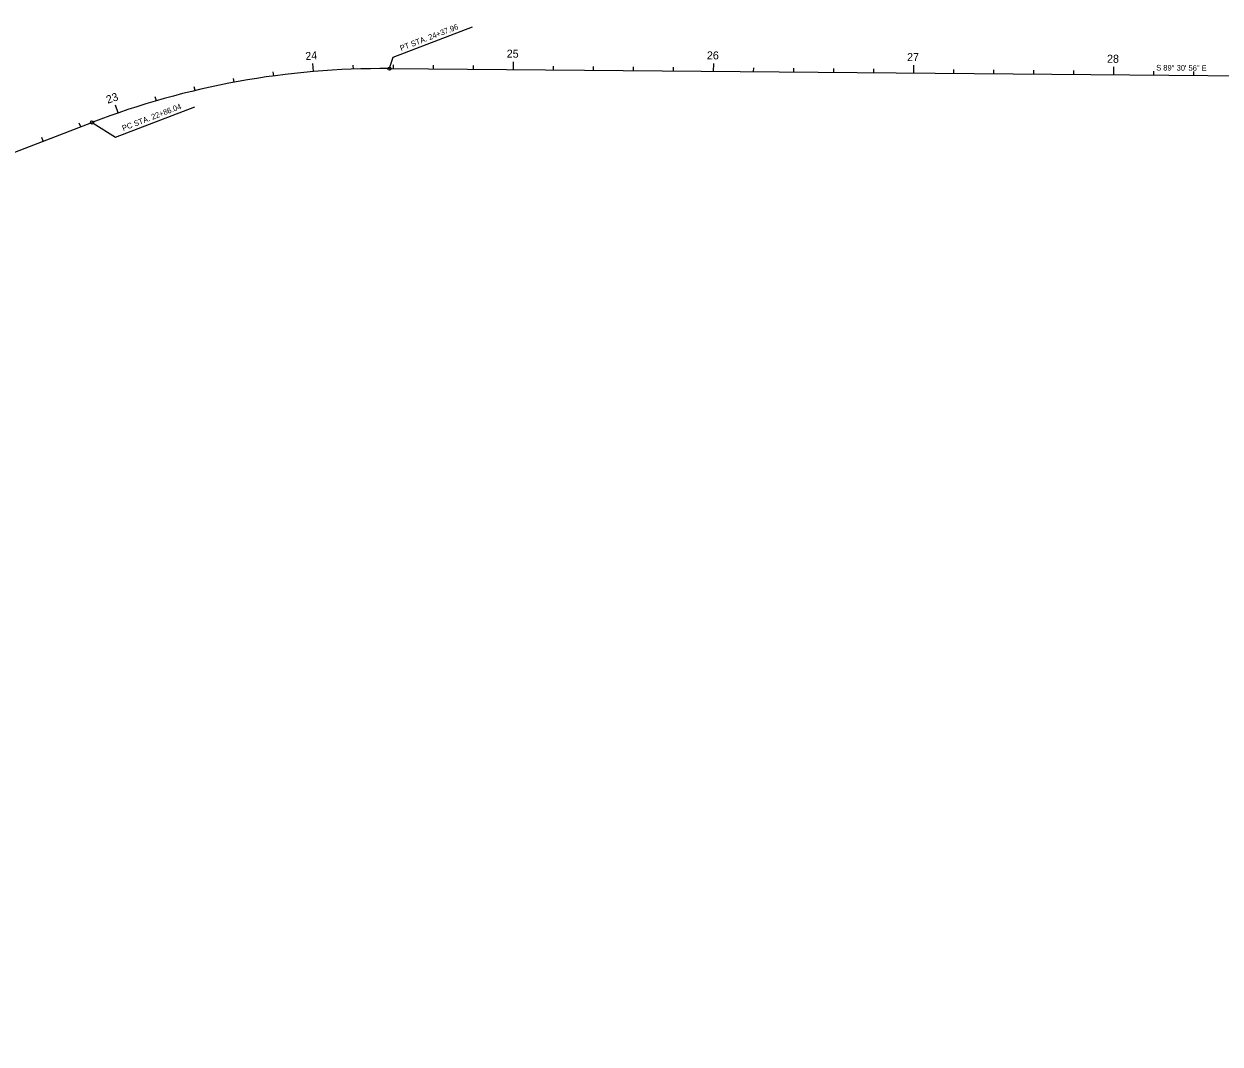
# Model space of a CAD drawing. Extents: x 509738 to 512118, y 1314883 to 1316817.
# Drawn here: x 510923 to 511521, y 1315134 to 1315644 of the extents above; entities that cross this region are included whole.
import ezdxf

# ---------------------------------------------------------------- set-up
doc = ezdxf.new("R2010")
doc.units = 0
for name, color, linetype in [('CLConst_dp', 7, 'Continuous'), ('CurveDataLabel_dp', 7, 'Continuous'), ('StationTicL_dp', 7, 'Continuous'), ('StationTicS_dp', 7, 'Continuous'), ('TextBLStation', 7, 'Continuous'), ('TextLabel', 7, 'Continuous')]:
    doc.layers.add(name, color=color, linetype=linetype)

msp = doc.modelspace()

# ---------------------------------------------------------------- linework, layer by layer
at = {"layer": 'CLConst_dp'}
for p, q in [((511105.4, 1315621.62), (512116.98, 1315613.07)), ((509756.06, 1315134.11), (510956.77, 1315594.74))]:
    msp.add_line(p, q, dxfattribs=at)
msp.add_arc((511101.97, 1315216.26), 405.38, 89.51549, 110.98867, dxfattribs=at)
at = {"layer": 'CurveDataLabel_dp'}
for p, q in [((511107.32, 1315627.37), (511146.94, 1315642.57)), ((511105.65, 1315622.38), (511107.32, 1315627.37)), ((510968.48, 1315587.39), (511008.11, 1315602.6)), ((510957.45, 1315594.32), (510968.48, 1315587.39))]:
    msp.add_line(p, q, dxfattribs=at)
for centre in [(511105.4, 1315621.62), (510956.77, 1315594.74)]:
    msp.add_circle(centre, 0.8, dxfattribs=at)
at = {"layer": 'StationTicL_dp'}
for p, q in [((511067.48, 1315620.17), (511067.13, 1315624.15)), ((511167.43, 1315621.1), (511167.46, 1315625.1)), ((511267.43, 1315620.25), (511267.46, 1315624.25)), ((511367.42, 1315619.41), (511367.46, 1315623.41)), ((511467.42, 1315618.56), (511467.45, 1315622.56)), ((510969.89, 1315599.52), (510968.59, 1315603.3))]:
    msp.add_line(p, q, dxfattribs=at)
at = {"layer": 'StationTicS_dp'}
for p, q in [((511087.44, 1315621.38), (511087.36, 1315623.38)), ((511107.43, 1315621.61), (511107.45, 1315623.61)), ((511127.43, 1315621.44), (511127.45, 1315623.44)), ((511147.43, 1315621.27), (511147.45, 1315623.27)), ((511187.43, 1315620.93), (511187.45, 1315622.93)), ((511207.43, 1315620.76), (511207.45, 1315622.76)), ((511227.43, 1315620.59), (511227.45, 1315622.59)), ((511247.43, 1315620.42), (511247.45, 1315622.42)), ((511287.43, 1315620.09), (511287.44, 1315622.09)), ((511307.43, 1315619.92), (511307.44, 1315621.92)), ((511327.43, 1315619.75), (511327.44, 1315621.75)), ((511347.42, 1315619.58), (511347.44, 1315621.58)), ((511387.42, 1315619.24), (511387.44, 1315621.24)), ((511407.42, 1315619.07), (511407.44, 1315621.07)), ((511427.42, 1315618.9), (511427.44, 1315620.9)), ((511447.42, 1315618.73), (511447.44, 1315620.73)), ((511027.85, 1315614.81), (511027.49, 1315616.77)), ((511047.6, 1315617.98), (511047.33, 1315619.96)), ((511487.42, 1315618.39), (511487.44, 1315620.39)), ((511507.42, 1315618.23), (511507.44, 1315620.23)), ((511008.29, 1315610.67), (511007.83, 1315612.61)), ((510988.95, 1315605.57), (510988.39, 1315607.49)), ((510951.13, 1315592.58), (510950.42, 1315594.45)), ((510932.46, 1315585.42), (510931.74, 1315587.28))]:
    msp.add_line(p, q, dxfattribs=at)

# ---------------------------------------------------------------- texts
at = {"layer": 'CurveDataLabel_dp'}
for s, p in [('PT STA. 24+37.96', (511111.3, 1315630.4)), ('PC STA. 22+86.04', (510972.46, 1315590.42))]:
    msp.add_text(s, height=2.8, rotation=20.98867, dxfattribs=at).set_placement(p)
at = {"layer": 'TextBLStation'}
for s, rotation, p in [('24', 4.88115, (511063.58, 1315625.86)), ('25', 359.51549, (511164.03, 1315627.13)), ('26', 359.51549, (511264.05, 1315626.28)), ('27', 359.51549, (511364.09, 1315625.44)), ('28', 359.51549, (511464.01, 1315624.59)), ('23', 19.01499, (510964.65, 1315604.06))]:
    msp.add_text(s, height=4, rotation=rotation, dxfattribs=at).set_placement(p)
at = {"layer": 'TextLabel'}
msp.add_text('S 89%%d 30\' 56" E', height=2.8, rotation=359.51549, dxfattribs=at).set_placement((511488.58, 1315620.72))

doc.saveas('drawing.dxf')
